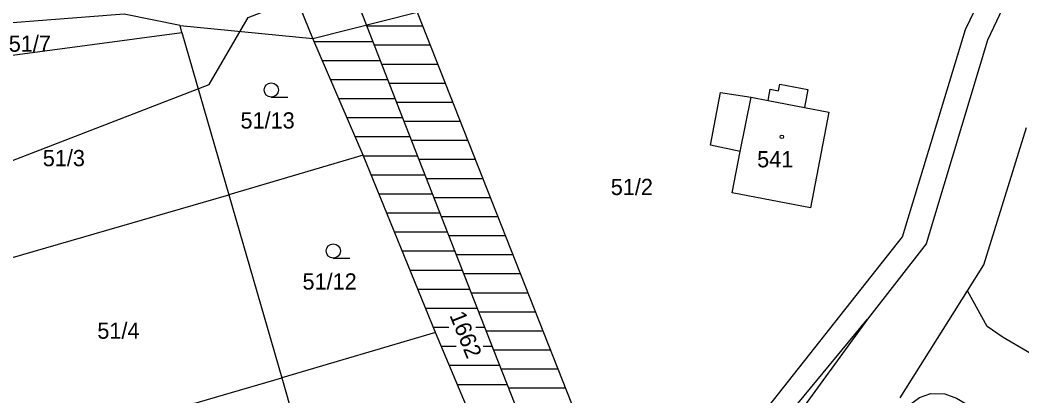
# Model space of a CAD drawing. Extents: x -553916 to -552953, y -1067470 to -1066637.
# Drawn here: x -553578.9 to -553473.7, y -1066947.3 to -1066907.8 of the extents above; entities that cross this region are included whole.
import ezdxf

# ---------------------------------------------------------------- set-up
doc = ezdxf.new("R2010")
doc.units = 0
for name, color, linetype in [('Hranice parcel', 7, 'Continuous'), ('Kolej', 7, 'Continuous'), ('Parcelní čísla', 7, 'Continuous'), ('Přejezd - štěrkové lože', 7, 'Continuous'), ('Vnitřní kresba', 7, 'Continuous'), ('Vrstva 1', 7, 'Continuous'), ('Značky budov', 7, 'Continuous'), ('Značky kultur', 7, 'Continuous')]:
    doc.layers.add(name, color=color, linetype=linetype)

msp = doc.modelspace()

# ---------------------------------------------------------------- linework, layer by layer
at = {"layer": 'Hranice parcel'}
for p, q in [((-553562.08, -1066908.37), (-553548.13, -1066909.75)), ((-553561.91, -1066909.12), (-553562.08, -1066908.37)), ((-553591.97, -1066913.14), (-553561.91, -1066909.12)), ((-553561.91, -1066909.12), (-553556.97, -1066926.17)), ((-553542.85, -1066922.01), (-553556.97, -1066926.17)), ((-553585.78, -1066934.51), (-553556.97, -1066926.17)), ((-553556.97, -1066926.17), (-553551.41, -1066945.38)), ((-553486.47, -1066947.45), (-553479.42, -1066936.25)), ((-553514.13, -1066968.51), (-553489.9, -1066939.2)), ((-553535.26, -1066940.6), (-553551.41, -1066945.38)), ((-553580.22, -1066953.72), (-553551.41, -1066945.38)), ((-553551.41, -1066945.38), (-553545.85, -1066964.59))]:
    msp.add_line(p, q, dxfattribs=at)
for points in [[(-553468.58, -1066891.47), (-553477.31, -1066909.92), (-553483.75, -1066931.3), (-553489.9, -1066939.2)], [(-553515.05, -1066965.6), (-553502.53, -1066951.2), (-553486.22, -1066930.56), (-553479.63, -1066908.8), (-553477.16, -1066903.7)], [(-553562.08, -1066908.37), (-553567.96, -1066907.21), (-553588.75, -1066908.8), (-553591.81, -1066911.32)], [(-553495.88, -1066927.52), (-553504.13, -1066925.96), (-553503.27, -1066921.61), (-553506.38, -1066920.95), (-553505.35, -1066915.4), (-553502.13, -1066915.91), (-553500.34, -1066916.26), (-553500.12, -1066915.07), (-553499.24, -1066915.24), (-553499.11, -1066914.55), (-553496.17, -1066915.11), (-553496.51, -1066917), (-553493.96, -1066917.49), (-553495.88, -1066927.52)], [(-553479.42, -1066936.25), (-553477.68, -1066933.49), (-553473.2, -1066919.09)], [(-553444.09, -1066959.55), (-553475.65, -1066941.14), (-553477.33, -1066939.99), (-553479.42, -1066936.25)], [(-553489.9, -1066939.2), (-553506.21, -1066961.59), (-553507.62, -1066963.64), (-553510.49, -1066967.37), (-553513.35, -1066970.96)], [(-553485.37, -1066948.09), (-553484.44, -1066947.42), (-553483.24, -1066947.01), (-553481.79, -1066947.03), (-553480.57, -1066947.51), (-553464.25, -1066957.05)]]:
    msp.add_lwpolyline(points, dxfattribs=at)
at = {"layer": 'Kolej'}
msp.add_lwpolyline([(-553503.32, -1067065.81), (-553502.68, -1067054.03), (-553502.76, -1067041.5), (-553503.63, -1067029.06), (-553504.76, -1067019.97), (-553506.18, -1067011.39), (-553508.33, -1067001.39), (-553510.95, -1066991.62), (-553512.92, -1066985.29), (-553515.65, -1066977.35), (-553517.42, -1066972.53), (-553519.16, -1066967.95), (-553522.89, -1066958.38), (-553529.1, -1066942.55), (-553538.69, -1066918.11), (-553542.91, -1066907.33), (-553546.69, -1066897.68), (-553555.03, -1066876.44), (-553564.64, -1066851.89), (-553574.24, -1066827.43), (-553583.19, -1066804.62)], dxfattribs=at)
at = {"layer": 'Přejezd - štěrkové lože'}
msp.add_lwpolyline([(-553598.54, -1066929.82), (-553559.03, -1066914.56), (-553554.95, -1066907.55), (-553544.41, -1066903.46)], dxfattribs=at)
at = {"layer": 'Vnitřní kresba'}
for p, q in [((-553503.27, -1066921.61), (-553502.13, -1066915.91)), ((-553500.34, -1066916.26), (-553496.51, -1066917))]:
    msp.add_line(p, q, dxfattribs=at)
at = {"layer": 'Vrstva 1'}
for p, q in [((-553548.13, -1066909.75), (-553550.91, -1066902.91)), ((-553548.13, -1066909.75), (-553537.18, -1066906.98)), ((-553542.48, -1066908.43), (-553536.61, -1066908.43)), ((-553542.85, -1066922.01), (-553548.13, -1066909.75)), ((-553548, -1066910.05), (-553541.84, -1066910.05)), ((-553541.69, -1066910.43), (-553535.82, -1066910.43)), ((-553547.14, -1066912.05), (-553541.06, -1066912.05)), ((-553540.91, -1066912.43), (-553535.03, -1066912.43)), ((-553546.28, -1066914.05), (-553540.27, -1066914.05)), ((-553540.13, -1066914.43), (-553534.25, -1066914.43)), ((-553545.42, -1066916.05), (-553539.49, -1066916.05)), ((-553539.34, -1066916.43), (-553533.46, -1066916.43)), ((-553544.55, -1066918.05), (-553538.71, -1066918.05)), ((-553538.56, -1066918.43), (-553532.67, -1066918.43)), ((-553543.69, -1066920.05), (-553537.92, -1066920.05)), ((-553537.78, -1066920.43), (-553531.88, -1066920.43)), ((-553535.26, -1066940.6), (-553542.85, -1066922.01)), ((-553542.83, -1066922.05), (-553537.14, -1066922.05)), ((-553536.99, -1066922.43), (-553531.09, -1066922.43)), ((-553542.02, -1066924.05), (-553536.35, -1066924.05)), ((-553536.21, -1066924.43), (-553530.31, -1066924.43)), ((-553541.2, -1066926.05), (-553535.57, -1066926.05)), ((-553535.42, -1066926.43), (-553529.52, -1066926.43)), ((-553540.38, -1066928.05), (-553534.79, -1066928.05)), ((-553534.64, -1066928.43), (-553528.73, -1066928.43)), ((-553539.57, -1066930.05), (-553534, -1066930.05)), ((-553533.85, -1066930.43), (-553527.94, -1066930.43)), ((-553538.75, -1066932.05), (-553533.22, -1066932.05)), ((-553533.07, -1066932.43), (-553527.16, -1066932.43)), ((-553537.93, -1066934.05), (-553532.43, -1066934.05)), ((-553532.29, -1066934.43), (-553526.37, -1066934.43)), ((-553537.12, -1066936.05), (-553531.65, -1066936.05)), ((-553531.5, -1066936.43), (-553525.58, -1066936.43)), ((-553536.3, -1066938.05), (-553530.86, -1066938.05)), ((-553530.72, -1066938.43), (-553524.79, -1066938.43)), ((-553535.48, -1066940.05), (-553533.88, -1066940.05)), ((-553531.04, -1066940.05), (-553530.08, -1066940.05)), ((-553527.43, -1066959.15), (-553535.26, -1066940.6)), ((-553529.93, -1066940.43), (-553524, -1066940.43)), ((-553534.65, -1066942.05), (-553533.09, -1066942.05)), ((-553530.27, -1066942.05), (-553529.3, -1066942.05)), ((-553529.15, -1066942.43), (-553523.22, -1066942.43)), ((-553533.8, -1066944.05), (-553528.51, -1066944.05)), ((-553528.36, -1066944.43), (-553522.43, -1066944.43)), ((-553532.96, -1066946.05), (-553527.73, -1066946.05)), ((-553527.58, -1066946.43), (-553521.64, -1066946.43))]:
    msp.add_line(p, q, dxfattribs=at)
msp.add_lwpolyline([(-553537.18, -1066906.98), (-553519.04, -1066953.03), (-553515.05, -1066965.6)], dxfattribs=at)
at = {"layer": 'Značky budov'}
msp.add_circle((-553498.9, -1066920.07), 0.175, dxfattribs=at)
at = {"layer": 'Značky kultur'}
for p, q in [((-553552.51, -1066915.9), (-553550.76, -1066915.9)), ((-553546, -1066932.8), (-553544.25, -1066932.8))]:
    msp.add_line(p, q, dxfattribs=at)
for centre in [(-553552.51, -1066915.15), (-553546, -1066932.05)]:
    msp.add_circle(centre, 0.75, dxfattribs=at)

# ---------------------------------------------------------------- texts
at = {"layer": 'Parcelní čísla'}
for s, p in [('51/7', (-553580.07, -1066911.14)), ('51/13', (-553555.74, -1066919.2)), ('51/3', (-553576.5, -1066923.15)), ('541', (-553501.49, -1066923.27)), ('51/2', (-553516.86, -1066926.18)), ('51/12', (-553549.23, -1066936.1)), ('51/4', (-553570.77, -1066941.26))]:
    msp.add_text(s, height=1.7, dxfattribs=at).set_placement(p)
at = {"layer": 'Vrstva 1'}
msp.add_text('1662', height=1.7, rotation=292, dxfattribs=at).set_placement((-553533.82, -1066938.79))

doc.saveas('drawing.dxf')
